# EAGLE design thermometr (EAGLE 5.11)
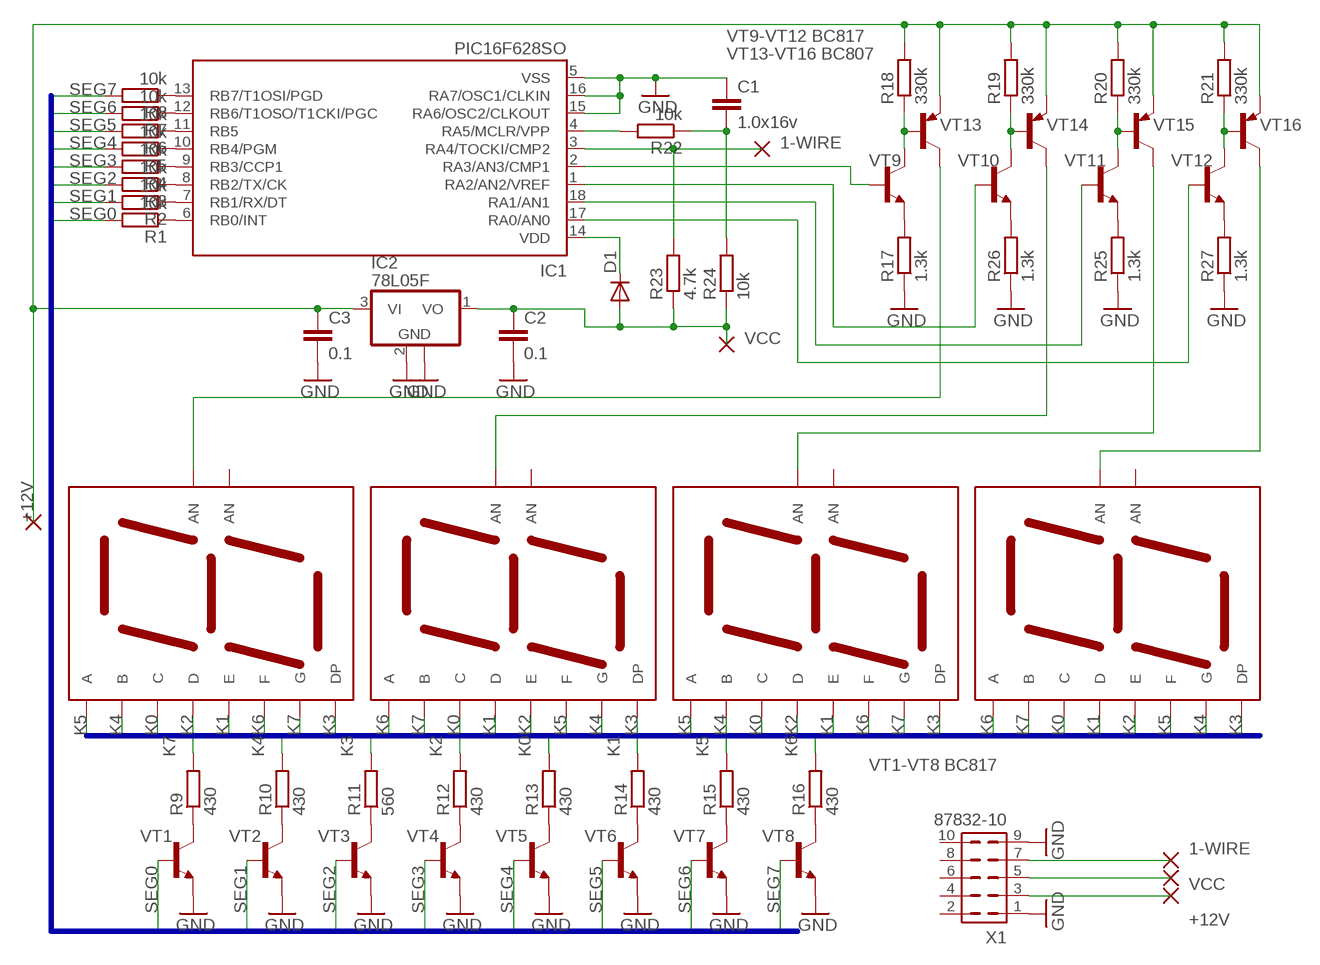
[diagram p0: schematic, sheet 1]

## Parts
C1  1.0x16v  C-EUC1206  [C1206]
C2  0.1  C-EUC1206  [C1206]
C3  0.1  C-EUC1206  [C1206]
D1  DIODE-DO-214AC  [DO-214AC]
IC1  PIC16F628SO  [SO-18W]
IC2  78L05F  [SOT89]
R1  10k  R-EU_M1206  [M1206]
R2  10k  R-EU_M1206  [M1206]
R3  10k  R-EU_M1206  [M1206]
R4  10k  R-EU_M1206  [M1206]
R5  10k  R-EU_M1206  [M1206]
R6  10k  R-EU_M1206  [M1206]
R7  10k  R-EU_M1206  [M1206]
R8  10k  R-EU_M1206  [M1206]
R9  430  R-EU_M1206  [M1206]
R10  430  R-EU_M1206  [M1206]
R11  560  R-EU_M1206  [M1206]
R12  430  R-EU_M1206  [M1206]
R13  430  R-EU_M1206  [M1206]
R14  430  R-EU_M1206  [M1206]
R15  430  R-EU_M1206  [M1206]
R16  430  R-EU_M1206  [M1206]
R17  1.3k  R-EU_M1206  [M1206]
R18  330k  R-EU_M1206  [M1206]
R19  330k  R-EU_M1206  [M1206]
R20  330k  R-EU_M1206  [M1206]
R21  330k  R-EU_M1206  [M1206]
R22  10k  R-EU_M1206  [M1206]
R23  4.7k  R-EU_M1206  [M1206]
R24  10k  R-EU_M1206  [M1206]
R25  1.3k  R-EU_M1206  [M1206]
R26  1.3k  R-EU_M1206  [M1206]
R27  1.3k  R-EU_M1206  [M1206]
U$1  SA10-21  [SX10-21]
U$2  SA10-21  [SX10-21]
U$3  SA10-21  [SX10-21]
U$4  SA10-21  [SX10-21]
VT1  BC817  BC817-16-NPN-SOT23-BEC  [SOT23-BEC]
VT2  BC817  BC817-16-NPN-SOT23-BEC  [SOT23-BEC]
VT3  BC817  BC817-16-NPN-SOT23-BEC  [SOT23-BEC]
VT4  BC817  BC817-16-NPN-SOT23-BEC  [SOT23-BEC]
VT5  BC817  BC817-16-NPN-SOT23-BEC  [SOT23-BEC]
VT6  BC817  BC817-16-NPN-SOT23-BEC  [SOT23-BEC]
VT7  BC817  BC817-16-NPN-SOT23-BEC  [SOT23-BEC]
VT8  BC817  BC817-16-NPN-SOT23-BEC  [SOT23-BEC]
VT9  BC817  BC817-16-NPN-SOT23-BEC  [SOT23-BEC]
VT10  BC817  BC817-16-NPN-SOT23-BEC  [SOT23-BEC]
VT11  BC817  BC817-16-NPN-SOT23-BEC  [SOT23-BEC]
VT12  BC817  BC817-16-NPN-SOT23-BEC  [SOT23-BEC]
VT13  BC807  BC807-16LT1-PNP-SOT23-BEC  [SOT23-BEC]
VT14  BC807  BC807-16LT1-PNP-SOT23-BEC  [SOT23-BEC]
VT15  BC807  BC807-16LT1-PNP-SOT23-BEC  [SOT23-BEC]
VT16  BC807  BC807-16LT1-PNP-SOT23-BEC  [SOT23-BEC]
X1  87832-10  [87832-10]

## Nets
1-WIRE: IC1.3(RA4/TOCKI/CMP2) R23.2 X1.7
+12V: C3.1 IC2.3(VI) R18.2 R19.2 R20.2 R21.2 VT13.E VT14.E VT15.E VT16.E X1.3
GND: C1.1 C2.2 C3.2 IC1.5(VSS) IC1.15(RA6/OSC2/CLKOUT) IC1.16(RA7/OSC1/CLKIN) IC2.2(GND) IC2.2@1(GND) R17.1 R25.1 R26.1 R27.1 VT1.E VT2.E VT3.E VT4.E VT5.E VT6.E VT7.E VT8.E X1.1 X1.9
K0: R13.2 U$1.P$4(C) U$2.P$4(C) U$3.P$4(C) U$4.P$4(C)
K1: R14.2 U$1.P$1(E) U$2.P$2(D) U$3.P$1(E) U$4.P$2(D)
K2: R12.2 U$1.P$2(D) U$2.P$1(E) U$3.P$2(D) U$4.P$1(E)
K3: R11.2 U$1.P$5(DP) U$2.P$5(DP) U$3.P$5(DP) U$4.P$5(DP)
K4: R10.2 U$1.P$6(B) U$2.P$10(G) U$3.P$6(B) U$4.P$10(G)
K5: R15.2 U$1.P$7(A) U$2.P$9(F) U$3.P$7(A) U$4.P$9(F)
K6: R16.2 U$1.P$9(F) U$2.P$7(A) U$3.P$9(F) U$4.P$7(A)
K7: R9.2 U$1.P$10(G) U$2.P$6(B) U$3.P$10(G) U$4.P$6(B)
N$1: IC1.6(RB0/INT) R1.1
N$2: IC1.7(RB1/RX/DT) R2.1
N$3: IC1.8(RB2/TX/CK) R3.1
N$4: IC1.9(RB3/CCP1) R4.1
N$5: IC1.10(RB4/PGM) R5.1
N$6: IC1.11(RB5) R6.1
N$7: IC1.12(RB6/T1OSO/T1CKI/PGC) R7.1
N$8: IC1.13(RB7/T1OSI/PGD) R8.1
N$9: R9.1 VT1.C
N$10: R10.1 VT2.C
N$11: R11.1 VT3.C
N$12: R12.1 VT4.C
N$13: R13.1 VT5.C
N$14: R14.1 VT6.C
N$15: R15.1 VT7.C
N$16: R16.1 VT8.C
N$17: R27.2 VT12.E
N$18: R18.1 VT9.C VT13.B
N$19: R19.1 VT10.C VT14.B
N$20: R20.1 VT11.C VT15.B
N$21: R21.1 VT12.C VT16.B
N$23: IC1.2(RA3/AN3/CMP1) VT9.B
N$24: IC1.1(RA2/AN2/VREF) VT10.B
N$25: IC1.18(RA1/AN1) VT11.B
N$26: IC1.17(RA0/AN0) VT12.B
N$27: U$1.P$8(AN) VT13.C
N$28: U$2.P$8(AN) VT14.C
N$29: U$3.P$8(AN) VT15.C
N$30: U$4.P$8(AN) VT16.C
N$31: IC1.4(RA5/MCLR/VPP) R22.2
N$34: C1.2 R22.1 R24.2
N$35: R17.2 VT9.E
N$36: R26.2 VT10.E
N$37: R25.2 VT11.E
N$38: D1.C IC1.14(VDD)
SEG0: R1.2 VT1.B
SEG1: R2.2 VT2.B
SEG2: R3.2 VT3.B
SEG3: R4.2 VT4.B
SEG4: R5.2 VT5.B
SEG5: R6.2 VT6.B
SEG6: R7.2 VT7.B
SEG7: R8.2 VT8.B
VCC: C2.1 D1.A IC2.1(VO) R23.1 R24.1 X1.5
Unconnected: U$1.P$3(AN) U$2.P$3(AN) U$3.P$3(AN) U$4.P$3(AN) X1.2 X1.4 X1.6 X1.8 X1.10

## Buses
SEG[0..7]
K[0..7]

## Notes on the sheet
- VT9-VT12 BC817
- VT13-VT16 BC807
- VT1-VT8 BC817

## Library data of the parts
C1-C3 = rcl:C-EU: CAPACITOR, European symbol
D1 = diode:DIODE-: DIODE
IC1 = microchip:PIC16F62*: FLASH-Based 8-Bit CMOS Microcontroller Source: http://ww1.microchip.com/downloads/en/DeviceDoc/40300C.pdf
IC2 = linear:78L*: POSITOIV-VOLTAGE REGULATORS Output up to 100 mA Source: http://focus.ti.com/lit/ds/symlink/ua78l05.pdf
R1-R27 = rcl:R-EU_: RESISTOR, European symbol
U$1-U$4 = A564:SA10-21
VT1-VT12 = transistor:*-NPN-: NPN Transistror BF959 corrected 2008.03.06
VT13-VT16 = transistor:*-PNP-: PNP Transistror
X1 = con-molex:87832-10: Milli-Grid Header 2.00mm (.079") Pitch

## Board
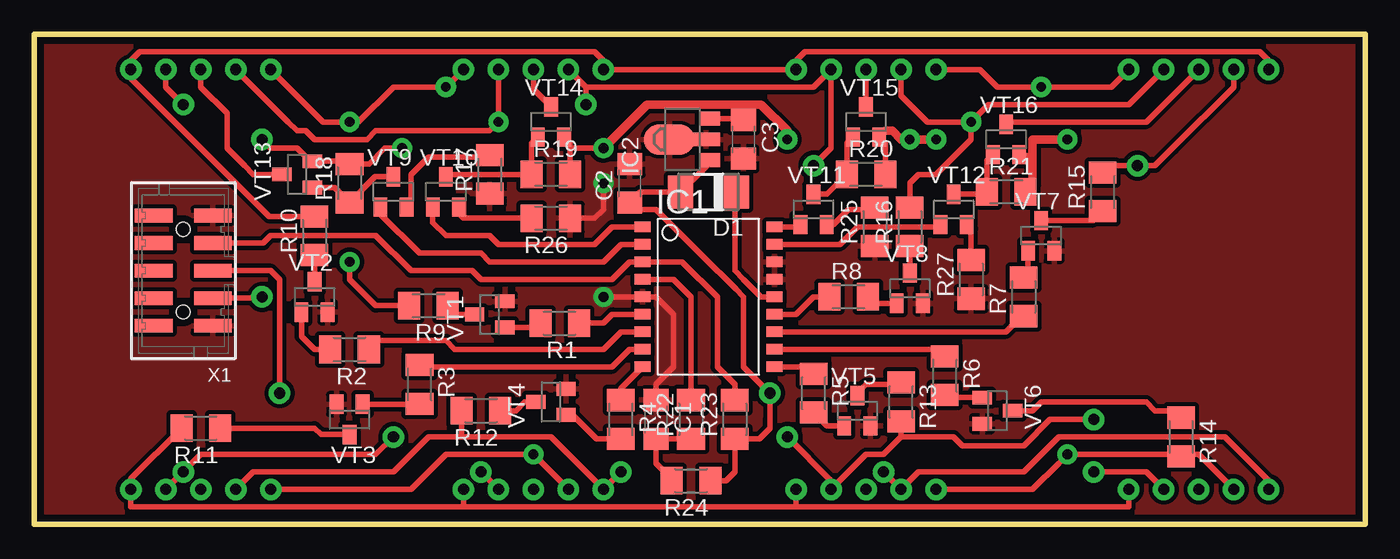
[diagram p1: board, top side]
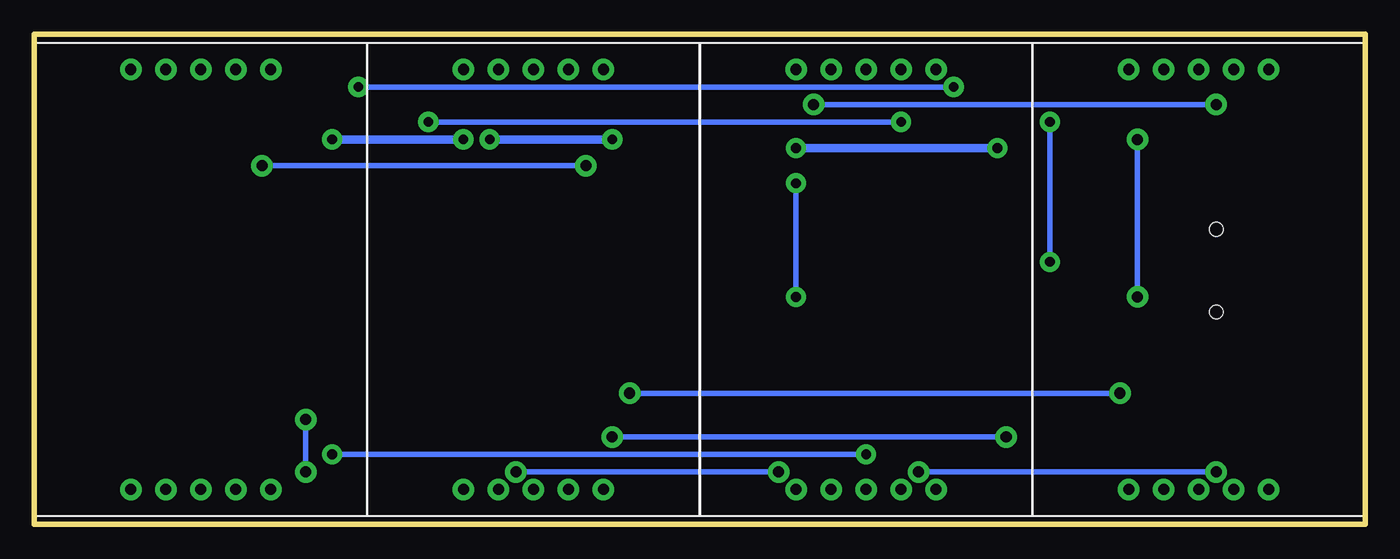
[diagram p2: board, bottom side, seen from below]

Size 96.52 x 35.56 mm. Coordinates in mm from the lower left corner, seen from the top.
Outline: 0,35.55 0,35.56
Outline: 0,35.56 0,35.55
Outline: 0,35.55 0,0 96.52,0 96.52,35.56 0,35.56
Copper layers (1*16): Top 0.035mm / dielectric 1.5mm / Bottom 0.035mm
Design rules "default *": minimum track width 10mil, minimum drill 24mil, track to track 8mil, track to pad 8mil, pad to pad 8mil, via to via 8mil, smd to smd 8mil, copper to edge 20mil, drill to drill 8mil, minimum pad ring 15mil, minimum via ring 15mil, stop-mask expansion 4mil, vias tented up to drill 0mil, thermal gap 10mil

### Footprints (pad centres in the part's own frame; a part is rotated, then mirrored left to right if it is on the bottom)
C1206 = smd 1.6 x 1.8: 1 -1.4,0; 2 1.4,0
DO-214AC = smd 1.8 x 2.4: A 2.025,0; C -2.025,0
SO-18W = smd 0.762 x 1.143: 1 -5.08,-4.788; 2 -3.81,-4.788; 3 -2.54,-4.788; 4 -1.27,-4.788; 5 0,-4.788; 6 1.27,-4.788; 7 2.54,-4.788; 8 3.81,-4.788; 9 5.08,-4.788; 10 5.08,4.788; 11 3.81,4.788; 12 2.54,4.788; 13 1.27,4.788; 14 0,4.788; 15 -1.27,4.788; 16 -2.54,4.788; 17 -3.81,4.788; 18 -5.08,4.788
SOT89 = smd 1 x 1.5: 1 -1.499,-1.981; 3 1.499,-1.981 | smd 1 x 2: 2 0,-1.727 | smd 2.2 x 3.7: 2@1 0,0.94
M1206 = smd 1.6 x 2: 1 -1.4,0; 2 1.4,0
SX10-21 = drill 0.8 round: P$1 -5.08,0; P$2 -2.54,0; P$3 0,0; P$4 2.54,0; P$5 5.08,0; P$6 5.08,30.48; P$7 2.54,30.48; P$8 0,30.48; P$9 -2.54,30.48; P$10 -5.08,30.48
SOT23-BEC = smd 1 x 1.4: B -0.95,-1.1; C 0,1.1; E 0.95,-1.1
87832-10 = smd 1 x 2.75: 1 -4,-2.15; 2 -4,2.15; 3 -2,-2.15; 4 -2,2.15; 5 0,-2.15; 6 0,2.15; 7 2,-2.15; 8 2,2.15; 9 4,-2.15; 10 4,2.15 | hole 1: -3,0; 3,0

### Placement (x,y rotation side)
C1  45.09,7.62 270 top
C2  43.18,24.77 90 top
C3  51.44,27.94 270 top
D1  48.9,24.13 180 top
IC1  48.9,16.51 270 top
IC2  46.99,27.94 90 top
R1  38.1,14.61 180 top
R2  22.86,12.7 180 top
R3  27.94,10.16 270 top
R4  42.55,7.62 270 top
R5  56.52,9.53 270 top
R6  66.04,10.79 270 top
R7  71.75,16.51 90 top
R8  59.05,16.51 0 top
R9  28.58,15.88 180 top
R10  20.32,20.96 90 top
R11  12.06,6.99 180 top
R12  32.38,8.26 180 top
R13  62.87,8.89 270 top
R14  83.19,6.35 270 top
R15  77.47,24.13 90 top
R16  63.5,21.59 90 top
R17  33.02,25.4 90 top
R18  22.86,24.77 90 top
R19  37.47,25.4 0 top
R20  60.33,25.4 0 top
R21  70.48,24.13 0 top
R22  47.62,7.62 90 top
R23  50.8,7.62 90 top
R24  47.62,3.18 180 top
R25  60.96,21.59 90 top
R26  37.47,22.23 180 top
R27  67.95,17.78 90 top
U$1  12.06,2.54 0 bottom
U$2  36.2,2.54 0 bottom
U$3  60.33,2.54 0 bottom
U$4  84.45,2.54 0 bottom
VT1  33.02,15.24 90 top
VT2  20.32,16.51 0 top
VT3  22.86,7.62 180 top
VT4  37.47,8.89 90 top
VT5  59.69,8.26 0 top
VT6  69.85,8.26 270 top
VT7  73.03,20.96 0 top
VT8  63.5,17.14 0 top
VT9  26.04,24.13 0 top
VT10  29.85,24.13 0 top
VT11  56.52,22.86 0 top
VT12  66.67,22.86 0 top
VT13  19.05,25.4 90 top
VT14  37.47,29.21 0 top
VT15  60.33,29.21 0 top
VT16  70.48,27.94 0 top
X1  10.79,18.41 90 top

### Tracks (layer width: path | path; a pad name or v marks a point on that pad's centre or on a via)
1-WIRE
  Top 0.406: R23.2 50.8,10.16 49.53,11.43 49.53,16.51 46.99,19.05 IC1.3 43.18,19.05 41.91,17.78 32.38,17.78 31.75,18.41 27.3,18.41 24.77,20.96 17.14,20.96 16.61,20.41 X1.7
+12V  (via drill 0.7, 0.8)
  Top 0.406: R20.2 61.73,27.66 VT15.E 61.74,28.57 | 71.44,26.98 VT16.E 71.61,26.67 | 72.39,24.64 R21.2 | 51.44,30.48 C3.1 51.34,29.44 IC2.3 | X1.3 16.41,16.41 v16.51,16.51 | 38.87,27.3 R19.2 | 38.87,27.3 38.87,27.66 VT14.E | v41.27,27.3 38.87,27.3 | v16.51,27.94 17.14,27.3 19.05,27.3 20.01,26.35 VT13.E 22.68,26.35 R18.2 24.26,26.16 25.4,27.3 v26.67,27.3
  Top 0.61: v41.27,27.3 42.55,28.57 44.45,30.48 51.44,30.48 52.7,30.48 54.61,28.57 v54.61,27.94 | 61.74,28.57 62.23,28.57 62.87,27.94 v63.5,27.94 v65.41,27.94 | 72.39,26.67 72.39,24.64 | 72.39,26.67 71.61,26.67 | v74.93,27.94 72.39,27.94 72.39,26.67
  Bottom 0.406: v16.51,16.51 v16.51,27.94
  Bottom 0.61: v26.67,27.3 v41.27,27.3 | v54.61,27.94 v63.5,27.94 | v65.41,27.94 v74.93,27.94
GND  (via drill 0.7)
  Top 0.406: C1.1 45.09,10.16 46.36,11.43 46.36,15.24 45.09,16.51 IC1.5 42.55,16.51 v41.27,16.51 | R26.1 40.01,22.23 40.64,22.23 41.27,22.86 v41.27,24.77
  Bottom 0.406: v41.27,24.77 41.27,17.78 v41.27,16.51
  pour Top (isolate 0.305): 0,34.92 0,0.64 96.52,0.64 96.52,34.92
K0  (via drill 0.8)
  Top 0.406: U$1.P$4 v10.79,3.81 12.06,5.08 24.77,5.08 v26.04,6.35 | v32.38,3.81 U$2.P$4 | 62.87,6.35 61.59,5.08 60.33,5.08 U$3.P$4 57.79,3.18 v54.61,6.35 | 62.87,6.35 R13.2 | 62.87,6.35 66.67,6.35 67.31,5.71 71.75,5.71 73.66,7.62 v76.84,7.62 | v76.84,3.81 80.64,3.81 U$4.P$4
  Bottom 0.406: v10.79,3.81 v32.38,3.81 | v76.84,7.62 v76.84,3.81 | v26.04,6.35 v54.61,6.35
K1  (via drill 0.7)
  Top 0.406: 83.19,5.08 v74.93,5.08 74.3,4.45 72.39,2.54 U$3.P$1 | 83.19,5.08 84.45,5.08 U$4.P$2 | 83.19,5.08 R14.2 | U$1.P$1 27.3,2.54 29.85,5.08 v36.2,5.08 37.47,3.81 U$2.P$2
  Bottom 0.406: v36.2,5.08 v74.93,5.08
K2  (via drill 0.8)
  Top 0.406: 31.12,6.35 29.85,6.35 28.58,6.35 27.3,5.08 26.04,3.81 15.88,3.81 U$1.P$2 | 31.12,6.35 37.47,6.35 U$2.P$1 v42.55,3.81 | R12.2 30.98,6.48 31.12,6.35 | U$4.P$1 89.53,3.18 86.36,6.35 74.3,6.35 71.75,3.81 64.13,3.81 U$3.P$2 v61.59,3.81
  Bottom 0.406: v42.55,3.81 v61.59,3.81
K3
  Top 0.406: 31.12,1.27 U$2.P$5 | 31.12,1.27 6.99,1.27 U$1.P$5 6.99,3.18 6.99,3.31 R11.2 | 55.25,1.27 U$3.P$5 | 31.12,1.27 55.25,1.27 | U$4.P$5 79.38,1.27 55.25,1.27
K4
  Top 0.406: R10.2 17.02,22.36 6.99,32.38 U$1.P$6 6.99,33.65 7.62,34.29 40.64,34.29 41.27,33.65 U$2.P$10 U$3.P$6 55.25,33.65 55.88,34.29 88.9,34.29 89.53,33.65 U$4.P$10
K5  (via drill 0.8)
  Top 0.406: R15.2 77.6,25.53 78.11,26.04 v80.01,26.04 81.28,26.04 82.55,27.3 87,31.75 U$4.P$9 | 40.01,31.75 U$2.P$9 | 40.01,31.75 42.55,31.75 56.52,31.75 U$3.P$7 57.79,27.3 v56.52,26.04 | U$1.P$7 9.53,31.75 v10.79,30.48 | v40.01,30.48 40.01,31.75
  Bottom 0.406: v56.52,26.04 v80.01,26.04 | v10.79,30.48 v40.01,30.48
K6  (via drill 0.7)
  Top 0.406: R16.2 63.5,24.13 63.5,24.77 64.13,25.4 65.41,25.4 67.95,27.94 v67.95,29.21 | U$2.P$7 v33.66,29.21 33.02,28.57 24.77,28.57 24.13,27.94 20.32,27.94 19.69,28.57 19.05,28.57 18.42,29.21 U$1.P$9 | U$4.P$7 79.38,30.48 69.22,30.48 v67.95,29.21 | v67.95,29.21 64.77,29.21 62.87,31.11 U$3.P$9
  Bottom 0.406: v33.66,29.21 v67.95,29.21
K7  (via drill 0.7)
  Top 0.406: R9.2 24.77,15.88 22.86,17.78 v22.86,19.05 | U$2.P$6 v29.85,31.75 26.04,31.75 23.5,29.21 v22.86,29.21 20.96,29.21 18.42,31.75 U$1.P$10 | U$3.P$10 68.58,33.02 69.85,31.75 v73.03,31.75 78.11,31.75 U$4.P$6
  Bottom 0.406: v29.85,31.75 v73.03,31.75 | v22.86,19.05 v22.86,29.21
N$1
  Top 0.406: R1.1 41.27,14.61 41.91,15.24 IC1.6
N$2
  Top 0.406: IC1.7 42.55,13.97 41.27,12.7 30.48,12.7 29.85,13.34 24.77,13.34 24.26,12.83 R2.1
N$3
  Top 0.406: IC1.8 43.18,12.7 41.91,11.43 35.56,11.43 28.07,11.43 R3.1
N$4
  Top 0.406: IC1.9 42.55,9.87 R4.1
N$5
  Top 0.406: R5.1 56.38,10.93 55.88,11.43 IC1.10
N$6
  Top 0.406: R6.1 65.91,12.2 65.41,12.7 IC1.11
N$7
  Top 0.406: R7.1 71.62,15.11 70.48,13.97 IC1.12
N$8
  Top 0.406: R8.1 56.52,16.51 55.25,15.24 IC1.13
N$9
  Top 0.406: VT1.C 30.61,15.24 R9.1
N$10
  Top 0.406: VT2.C R10.1
N$11
  Top 0.406: VT3.C 20.79,6.52 20.32,6.99 R11.1
N$12
  Top 0.406: VT4.C 35.56,8.89 34.93,8.26 R12.1
N$13
  Top 0.406: VT5.C 59.69,9.53 60.33,10.16 62.73,10.16 R13.1
N$14
  Top 0.406: VT6.C 72.39,8.26 73.03,8.89 80.64,8.89 81.28,8.26 82.68,8.26 R14.1
N$15
  Top 0.406: VT7.C 76.8,22.05 R15.1
N$16
  Top 0.406: VT8.C R16.1
N$17
  Top 0.406: VT12.E 67.95,21.44 R27.2
N$18
  Top 0.406: VT9.C 24.73,25.23 R18.1 21.78,24.45 VT13.B
N$19
  Top 0.406: VT14.B 36.06,27.66 R19.1 | R19.1 35.9,25.23 | VT10.C 29.68,25.23 29.85,25.4 R19.1
N$20
  Top 0.406: VT15.B 58.93,27.66 R20.1 57.48,23.96 VT11.C
N$21
  Top 0.406: R21.1 69.22,24 | VT16.B 69.09,26.39 R21.1 | VT12.C 68.92,23.96 R21.1
N$23
  Top 0.406: IC1.2 42.55,20.32 41.27,19.05 33.02,19.05 32.38,19.68 27.94,19.68 25.09,22.54 VT9.B
N$24
  Top 0.406: IC1.1 41.91,21.59 40.64,20.32 33.66,20.32 33.02,20.96 29.85,20.96 28.89,21.91 VT10.B
N$25
  Top 0.406: VT11.B 55.56,21.59 IC1.18
N$26
  Top 0.406: VT12.B 65.55,21.59 63.5,21.59 59.69,21.59 58.42,20.32 IC1.17
N$27
  Top 0.406: U$1.P$8 12.06,31.75 13.97,29.84 13.97,27.3 15.24,26.04 15.88,25.4 VT13.C
N$28
  Top 0.406: VT14.C 36.2,31.58 U$2.P$8
N$29
  Top 0.406: VT15.C U$3.P$8
N$30
  Top 0.406: VT16.C 70.66,29.21 77.3,29.21 80.64,29.21 U$4.P$8
N$31
  Top 0.406: IC1.4 46.36,17.78 47.62,16.51 47.62,11.43 47.62,10.16 R22.2
N$34
  Top 0.406: R24.2 46.23,3.31 45.09,4.45 C1.2 46.36,6.22 R22.1
N$35
  Top 0.406: VT9.E 26.98,23.18 27.3,23.5 27.3,25.4 28.58,26.67 32.89,26.67 R17.2
N$36
  Top 0.406: VT10.E 30.8,22.55 31.12,22.23 R26.2
N$37
  Top 0.406: VT11.E 57.95,21.76 59.05,22.86 60.83,22.86 R25.2
N$38
  Top 0.406: IC1.14 52.7,16.51 51.44,17.78 50.8,18.41 50.8,24.01 D1.C
SEG0
  Top 0.406: VT1.B 36.38,14.29 R1.2
SEG1
  Top 0.406: VT2.B 19.37,13.65 20.32,12.7 R2.2
SEG2
  Top 0.406: VT3.B 27.9,8.72 R3.2
SEG3
  Top 0.406: VT4.B 39.05,7.94 40.64,6.35 40.77,6.22 R4.2
SEG4
  Top 0.406: VT5.B 57.48,7.16 R5.2
SEG5
  Top 0.406: VT6.B 66.23,9.21 R6.2
SEG6
  Top 0.406: VT7.B 72.08,18.23 R7.2
SEG7
  Top 0.406: VT8.B 60.92,16.05 R8.2
VCC  (via drill 0.8)
  Top 0.406: v53.34,9.53 51.44,11.43 51.44,16.51 50.88,17.07 48.39,19.55 45.09,22.86 43.69,22.86 C2.1 43.95,24.13 D1.A 48.97,26.23 IC2.1 | 53.34,7.62 53.34,6.99 52.58,6.22 R23.1 50.8,3.81 50.16,3.18 R24.1 | v53.34,9.53 53.34,7.62 | X1.5 17.14,18.41 17.78,17.78 v17.78,9.53 | v53.34,9.53 53.34,7.62
  Bottom 0.406: v17.78,9.53 v53.34,9.53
